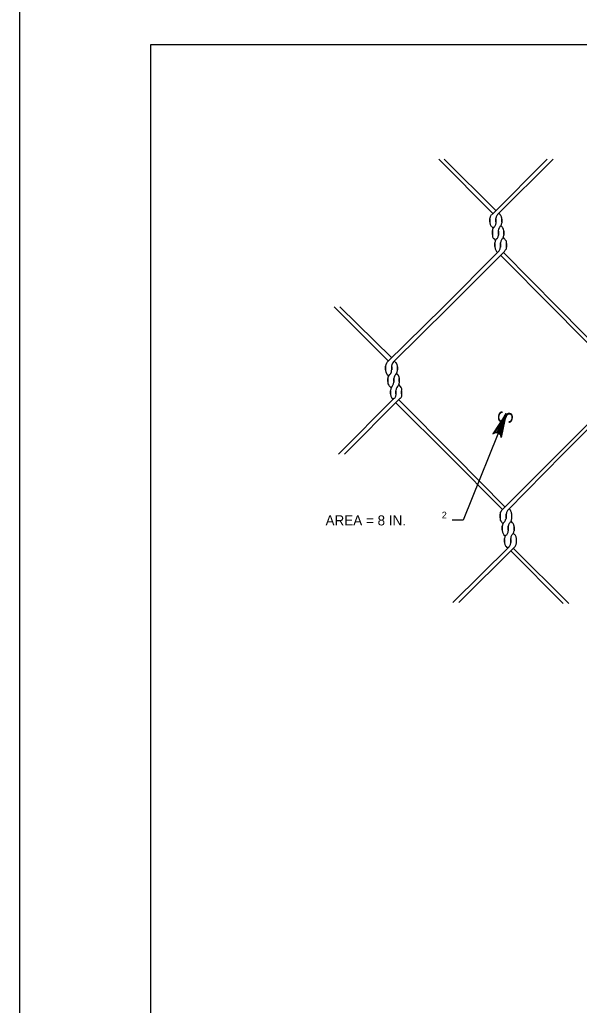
# Model space of a CAD drawing. Extents: x 3 to 3592, y -602 to 1171.
# Drawn here: x 2.5 to 169.2, y 276.1 to 569.3 of the extents above; entities that cross this region are included whole.
import ezdxf

# ---------------------------------------------------------------- set-up
doc = ezdxf.new("R2010")
doc.units = 0
for name, color, linetype in [('1', 7, 'Continuous'), ('2', 7, 'Continuous'), ('3', 7, 'Continuous'), ('P', 7, 'Continuous'), ('PLT-BNDY', 7, 'Continuous')]:
    doc.layers.add(name, color=color, linetype=linetype)

msp = doc.modelspace()

# ---------------------------------------------------------------- linework, layer by layer
at = {"layer": '1'}
msp.add_lwpolyline([(827.51, -2.17), (827.51, 561.83), (41.51, 561.83), (41.51, -2.17), (827.51, -2.17), (827.51, 24.19), (627.51, 24.19), (627.51, 88.87), (827.51, 88.87), (827.51, 117.83), (627.51, 117.83), (627.51, -2.17), (706.31, -2.17), (706.31, 24.19), (706.31, -2.17), (783.31, -2.17), (783.31, 24.19), (783.31, 11.88), (827.51, 11.88)], dxfattribs=at)
at = {"layer": '2'}
msp.add_lwpolyline([(147.4, 452.17), (145.92, 445.06), (145.78, 445.72), (147.4, 452.17), (145.44, 446.16), (145.03, 446.42), (147.4, 452.17), (144.56, 446.52), (144.01, 446.44), (147.4, 452.17), (143.45, 446.08), (144.01, 446.44), (144.56, 446.52), (145.03, 446.42), (145.44, 446.16), (145.78, 445.72)], dxfattribs=at)
at = {"layer": 'P'}
for points in [[(143.38, 511.67), (127.32, 527.82)], [(144.29, 512.58), (128.95, 527.82)], [(143.17, 511.36), (159.63, 527.82)], [(144.8, 511.36), (161.36, 527.82)], [(143.07, 511.36), (142.97, 511.26), (142.87, 511.06), (142.67, 510.65), (142.67, 510.55), (142.56, 510.24), (142.56, 510.14)], [(144.8, 511.36), (144.8, 511.26), (144.6, 511.06), (144.39, 510.65), (144.39, 510.55), (144.29, 510.24), (144.29, 510.14)], [(145.61, 511.36), (145.31, 511.67)], [(146.12, 510.14), (146.12, 510.24), (146.02, 510.55), (146.02, 510.65), (145.82, 511.06), (145.61, 511.26), (145.61, 511.36)], [(142.56, 509.23), (142.56, 510.14)], [(142.56, 509.94), (142.56, 508.92)], [(142.56, 508.92), (142.56, 508.82), (142.67, 508.62), (142.67, 508.42), (142.87, 508.01), (142.97, 507.91), (143.07, 507.7)], [(143.17, 507.7), (143.38, 507.4)], [(143.78, 507.7), (143.68, 507.5), (143.48, 507.4), (143.28, 506.89), (143.28, 506.79), (143.28, 506.59), (143.28, 506.38)], [(143.89, 507.7), (143.99, 507.91), (144.09, 508.01), (144.29, 508.42), (144.29, 508.62), (144.39, 508.82), (144.39, 508.92)], [(144.29, 509.23), (144.29, 510.14)], [(144.29, 509.23), (144.29, 510.14)], [(144.29, 509.94), (144.29, 508.92)], [(144.29, 509.94), (144.29, 508.92)], [(145.51, 507.7), (145.41, 507.5), (145.31, 507.4), (145.1, 506.89), (145.1, 506.79), (145, 506.59), (145, 506.38)], [(145.61, 507.7), (145.61, 507.91), (145.82, 508.01), (146.02, 508.42), (146.02, 508.62), (146.12, 508.82), (146.12, 508.92)], [(146.22, 507.7), (145.92, 508.01)], [(146.12, 509.23), (146.12, 510.14)], [(146.12, 509.94), (146.12, 508.92)], [(146.73, 506.38), (146.73, 506.59), (146.63, 506.79), (146.63, 506.89), (146.43, 507.4), (146.32, 507.5), (146.22, 507.7)], [(143.28, 505.47), (143.28, 506.59)], [(143.28, 506.38), (143.28, 505.27)], [(143.28, 505.27), (143.28, 505.16), (143.28, 504.96), (143.28, 504.76), (143.48, 504.35), (143.68, 504.25), (143.78, 504.05)], [(144.6, 504.05), (144.6, 504.25), (144.8, 504.35), (145, 504.76), (145, 504.96), (145.1, 505.16), (145.1, 505.27)], [(145.1, 505.47), (145.1, 506.59)], [(145.1, 505.47), (145.1, 506.59)], [(145.1, 506.38), (145.1, 505.27)], [(145.1, 506.38), (145.1, 505.27)], [(146.22, 504.05), (146.32, 504.25), (146.43, 504.35), (146.63, 504.76), (146.63, 504.96), (146.73, 505.16), (146.73, 505.27)], [(146.93, 504.15), (146.63, 504.55)], [(146.73, 505.47), (146.73, 506.59)], [(146.73, 506.38), (146.73, 505.27)], [(143.78, 504.15), (144.09, 503.74)], [(144.49, 504.15), (144.39, 504.05), (144.29, 503.84), (144.09, 503.44), (144.09, 503.23), (143.99, 503.03), (143.99, 502.93)], [(143.99, 501.81), (143.99, 502.93)], [(143.99, 502.73), (143.99, 501.61)], [(143.99, 501.71), (143.99, 501.61), (144.09, 501.41), (144.09, 501.2), (144.29, 500.8), (144.39, 500.59), (144.49, 500.49)], [(145.21, 500.49), (145.31, 500.59), (145.41, 500.8), (145.61, 501.2), (145.61, 501.41), (145.71, 501.61), (145.71, 501.71)], [(146.22, 504.15), (146.12, 504.05), (146.02, 503.84), (145.82, 503.44), (145.82, 503.23), (145.71, 503.03), (145.71, 502.93)], [(145.71, 501.81), (145.71, 502.93)], [(145.71, 501.81), (145.71, 502.93)], [(145.71, 502.73), (145.71, 501.61)], [(145.71, 502.73), (145.71, 501.61)], [(147.44, 502.93), (147.44, 503.03), (147.44, 503.23), (147.44, 503.44), (147.14, 503.84), (147.03, 504.05), (146.93, 504.15)], [(146.93, 500.49), (147.03, 500.59), (147.14, 500.8), (147.44, 501.2), (147.44, 501.41), (147.44, 501.61), (147.44, 501.71)], [(147.44, 501.81), (147.44, 502.93)], [(147.44, 502.73), (147.44, 501.61)], [(128.65, 483.83), (145.21, 500.49)], [(130.27, 483.83), (146.93, 500.39)], [(144.49, 500.39), (144.8, 500.08)], [(145.76, 499.22), (161.36, 483.52)], [(146.62, 500.08), (162.68, 483.83)], [(112.39, 467.78), (96.13, 483.93)], [(113.3, 468.69), (97.86, 483.93)], [(111.98, 467.47), (128.65, 483.83)], [(113.71, 467.47), (130.27, 483.83)], [(177.21, 467.57), (161.36, 483.52)], [(178.02, 468.28), (162.68, 483.83)], [(111.98, 467.47), (111.88, 467.27), (111.78, 467.17), (111.58, 466.66), (111.58, 466.56), (111.47, 466.35), (111.47, 466.15)], [(113.71, 467.47), (113.71, 467.27), (113.51, 467.17), (113.3, 466.66), (113.3, 466.56), (113.2, 466.35), (113.2, 466.15)], [(114.42, 467.47), (114.01, 467.67)], [(115.03, 466.15), (115.03, 466.35), (114.93, 466.56), (114.93, 466.66), (114.73, 467.17), (114.52, 467.27), (114.52, 467.47)], [(111.47, 465.13), (111.47, 466.25)], [(111.47, 466.05), (111.47, 465.13)], [(111.47, 465.03), (111.47, 464.83), (111.58, 464.63), (111.58, 464.52), (111.78, 464.02), (111.88, 463.91), (111.98, 463.81)], [(111.98, 463.81), (112.39, 463.51)], [(112.69, 463.81), (112.59, 463.61), (112.49, 463.51), (112.19, 463), (112.19, 462.9), (112.19, 462.7), (112.19, 462.49)], [(112.69, 463.81), (112.8, 463.91), (113, 464.02), (113.2, 464.52), (113.2, 464.63), (113.2, 464.83), (113.2, 465.03)], [(113.3, 465.13), (113.3, 466.25)], [(113.3, 465.13), (113.3, 466.25)], [(113.3, 466.05), (113.3, 465.13)], [(113.3, 466.05), (113.3, 465.13)], [(114.42, 463.81), (114.32, 463.61), (114.22, 463.51), (114.01, 463), (114.01, 462.9), (113.91, 462.7), (113.91, 462.49)], [(114.52, 463.81), (114.52, 463.91), (114.73, 464.02), (114.93, 464.52), (114.93, 464.63), (115.03, 464.83), (115.03, 465.03)], [(115.13, 463.71), (114.73, 464.12)], [(115.03, 465.13), (115.03, 466.25)], [(115.03, 466.05), (115.03, 465.13)], [(115.64, 462.49), (115.64, 462.7), (115.54, 462.9), (115.54, 463), (115.34, 463.51), (115.23, 463.61), (115.13, 463.81)], [(112.19, 461.68), (112.19, 462.59)], [(112.19, 462.39), (112.19, 461.48)], [(112.19, 461.48), (112.19, 461.37), (112.19, 461.17), (112.19, 460.97), (112.49, 460.56), (112.59, 460.36), (112.69, 460.26)], [(113.41, 460.26), (113.51, 460.36), (113.61, 460.56), (113.81, 460.97), (113.81, 461.17), (113.91, 461.37), (113.91, 461.48)], [(113.91, 461.68), (113.91, 462.59)], [(113.91, 461.68), (113.91, 462.59)], [(113.91, 462.39), (113.91, 461.48)], [(113.91, 462.39), (113.91, 461.48)], [(115.13, 460.26), (115.23, 460.36), (115.34, 460.56), (115.54, 460.97), (115.54, 461.17), (115.64, 461.37), (115.64, 461.48)], [(115.54, 461.68), (115.54, 462.59)], [(115.54, 462.39), (115.54, 461.48)], [(115.84, 460.26), (115.54, 460.66)], [(112.69, 460.26), (113, 459.95)], [(113.41, 460.26), (113.3, 460.16), (113.2, 459.95), (113, 459.55), (113, 459.34), (112.9, 459.14), (112.9, 459.04)], [(112.9, 458.02), (112.9, 458.94)], [(112.9, 458.83), (112.9, 457.92)], [(112.9, 457.82), (112.9, 457.72), (113, 457.51), (113, 457.31), (113.2, 456.9), (113.3, 456.7), (113.41, 456.6)], [(114.12, 456.6), (114.22, 456.7), (114.32, 456.9), (114.52, 457.31), (114.52, 457.51), (114.62, 457.72), (114.62, 457.82)], [(115.03, 460.26), (115.03, 460.16), (114.83, 459.95), (114.62, 459.55), (114.62, 459.34), (114.52, 459.14), (114.52, 459.04)], [(114.52, 458.02), (114.52, 458.94)], [(114.52, 458.02), (114.52, 458.94)], [(114.52, 458.83), (114.52, 457.92)], [(114.52, 458.83), (114.52, 457.92)], [(116.35, 459.04), (116.35, 459.14), (116.35, 459.34), (116.35, 459.55), (116.15, 459.95), (115.95, 460.16), (115.84, 460.26)], [(115.84, 456.6), (115.95, 456.7), (116.15, 456.9), (116.35, 457.31), (116.35, 457.51), (116.35, 457.72), (116.35, 457.82)], [(116.25, 458.02), (116.25, 458.94)], [(116.25, 458.83), (116.25, 457.92)], [(97.45, 440.04), (114.01, 456.7)], [(99.28, 440.04), (115.84, 456.7)], [(113.41, 456.7), (113.71, 456.19)], [(114.52, 455.38), (130.27, 439.63)], [(115.44, 456.19), (132, 439.53)], [(162.68, 439.94), (179.04, 456.29)], [(164, 439.73), (180.66, 456.29)], [(147.4, 452.17), (134.54, 420.43)], [(146.02, 423.27), (162.68, 439.94)], [(147.85, 423.38), (164.31, 440.04)], [(146.32, 423.58), (130.27, 439.63)], [(147.09, 424.34), (132, 439.53)], [(146.12, 423.38), (146.02, 423.27), (145.92, 423.07), (145.61, 422.67), (145.61, 422.56), (145.61, 422.26), (145.61, 422.16)], [(147.85, 423.38), (147.75, 423.27), (147.64, 423.07), (147.44, 422.67), (147.44, 422.56), (147.34, 422.26), (147.34, 422.16)], [(148.66, 423.38), (148.25, 423.78)], [(149.07, 422.16), (149.07, 422.26), (148.97, 422.56), (148.97, 422.67), (148.76, 423.07), (148.66, 423.38)], [(134.54, 420.43), (131.29, 420.43)], [(145.61, 421.14), (145.61, 422.26)], [(145.61, 422.06), (145.61, 420.94)], [(145.61, 420.94), (145.61, 420.84), (145.61, 420.63), (145.61, 420.43), (145.92, 420.02), (146.02, 419.92), (146.12, 419.72)], [(146.12, 419.72), (146.49, 419.33)], [(146.73, 419.72), (146.63, 419.62), (146.53, 419.41), (146.32, 419.01), (146.32, 418.91), (146.22, 418.6), (146.22, 418.5)], [(146.63, 419.62), (146.93, 419.92), (147.03, 420.02), (147.24, 420.43), (147.24, 420.63), (147.34, 420.84), (147.34, 420.94)], [(147.34, 421.14), (147.34, 422.26)], [(147.34, 421.14), (147.34, 422.26)], [(147.34, 422.06), (147.34, 420.94)], [(147.34, 422.06), (147.34, 420.94)], [(148.56, 419.72), (148.46, 419.62), (148.25, 419.41), (148.05, 419.01), (148.05, 418.91), (147.95, 418.6), (147.95, 418.5)], [(148.56, 419.72), (148.66, 419.92), (148.76, 420.02), (148.97, 420.43), (148.97, 420.63), (149.07, 420.84), (149.07, 420.94)], [(149.27, 419.62), (148.83, 420.16)], [(149.07, 421.04), (149.07, 422.16)], [(149.78, 418.5), (149.78, 418.6), (149.68, 418.91), (149.68, 419.01), (149.47, 419.41), (149.27, 419.62), (149.27, 419.72)], [(146.22, 417.59), (146.22, 418.6)], [(146.22, 418.4), (146.22, 417.28)], [(146.22, 417.38), (146.22, 417.28), (146.32, 417.08), (146.32, 416.87), (146.53, 416.47), (146.63, 416.26), (146.73, 416.06)], [(147.54, 416.16), (147.64, 416.26), (147.75, 416.47), (147.95, 416.87), (147.95, 417.08), (147.95, 417.28)], [(147.95, 417.59), (147.95, 418.6)], [(147.95, 417.59), (147.95, 418.6)], [(147.95, 418.4), (147.95, 417.28)], [(147.95, 418.4), (147.95, 417.28)], [(149.17, 416.16), (149.27, 416.26), (149.47, 416.47), (149.68, 416.87), (149.68, 417.08), (149.78, 417.28), (149.78, 417.38)], [(149.98, 416.06), (149.57, 416.47)], [(149.78, 417.59), (149.78, 418.6)], [(149.78, 418.4), (149.78, 417.28)], [(146.73, 416.06), (147.14, 415.76)], [(147.54, 416.16), (147.44, 415.96), (147.24, 415.86), (147.03, 415.45), (147.03, 415.25), (146.93, 415.05), (146.93, 414.94)], [(146.93, 413.93), (146.93, 414.94)], [(146.93, 414.64), (146.93, 413.72)], [(146.93, 413.72), (146.93, 413.62), (147.03, 413.42), (147.03, 413.22), (147.24, 412.81), (147.44, 412.61), (147.44, 412.51)], [(148.25, 412.51), (148.25, 412.61), (148.46, 412.81), (148.66, 413.22), (148.66, 413.42), (148.76, 413.62), (148.76, 413.72)], [(149.17, 416.16), (149.07, 415.96), (148.97, 415.86), (148.76, 415.45), (148.76, 415.25), (148.76, 414.94)], [(148.76, 413.93), (148.76, 414.94)], [(148.76, 413.72), (148.76, 414.74)], [(148.76, 414.64), (148.76, 413.83)], [(148.76, 414.64), (148.76, 413.83)], [(150.49, 414.94), (150.49, 415.05), (150.39, 415.25), (150.39, 415.45), (150.18, 415.86), (150.08, 415.96), (149.98, 416.16)], [(149.98, 412.51), (150.08, 412.61), (150.18, 412.81), (150.39, 413.22), (150.39, 413.42), (150.49, 413.62), (150.49, 413.72)], [(150.49, 413.72), (150.49, 414.94)], [(131.49, 395.94), (148.25, 412.51)], [(133.32, 395.94), (149.98, 412.51)], [(147.44, 412.51), (147.9, 412.16)], [(148.76, 411.29), (164.41, 395.64)], [(149.52, 412.05), (166.03, 395.64)]]:
    msp.add_lwpolyline(points, dxfattribs=at)
at = {"layer": 'PLT-BNDY'}
msp.add_lwpolyline([(2.51, 576.83), (843.51, 576.83), (843.51, -17.17), (2.51, -17.17)], close=True, dxfattribs=at)

# ---------------------------------------------------------------- texts
at = {"layer": '1'}
msp.add_text('S', height=4.35, rotation=261.8699, dxfattribs=at).set_placement((145.28, 453.3))
at = {"layer": '3'}
for s, height, p in [('2', 2, (128.21, 420.95)), ('AREA = 8 IN.', 3, (93.6, 418.87))]:
    msp.add_text(s, height=height, dxfattribs=at).set_placement(p)

doc.saveas('drawing.dxf')
